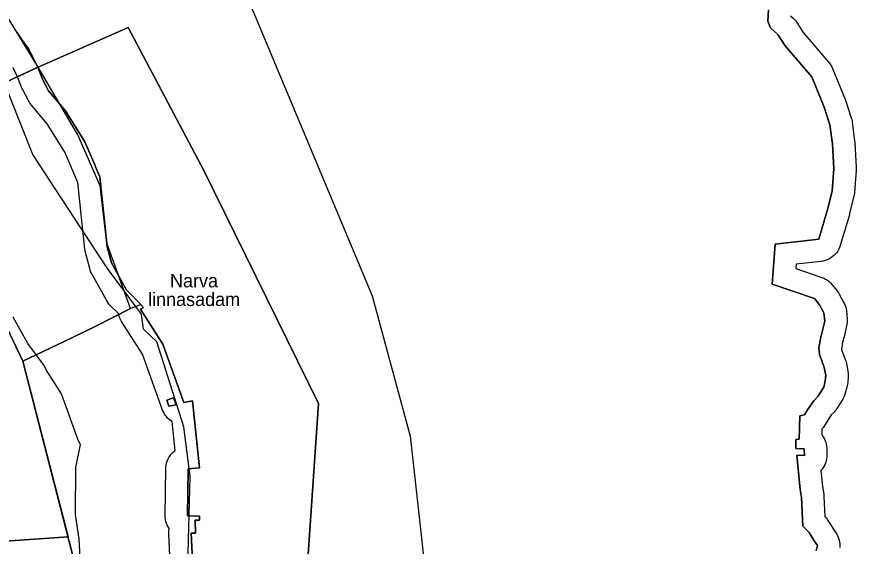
# Model space of a CAD drawing. Extents: x 728832 to 739469, y 6586263 to 6599699.
# Drawn here: x 738858.8 to 739233, y 6590183.4 to 6590419.5 of the extents above; entities that cross this region are included whole.
import ezdxf

# ---------------------------------------------------------------- set-up
doc = ezdxf.new("R2010")
doc.units = 0
for name, color, linetype in [('a_kalda_ekv', 7, 'Continuous'), ('a_kalda_veekaitsev', 7, 'Continuous'), ('a_piir', 7, 'Continuous'), ('a_veekogu_piir', 7, 'Continuous'), ('dp_hoonestus', 7, 'Continuous'), ('v_dp_kehtiv', 7, 'Continuous'), ('v_dp_situatsioon_tekst', 7, 'Continuous')]:
    doc.layers.add(name, color=color, linetype=linetype)

msp = doc.modelspace()

# ---------------------------------------------------------------- linework, layer by layer
at = {"layer": 'a_kalda_ekv'}
msp.add_lwpolyline([(738857.47, 6590092.24), (738873.8, 6590121.13), (738876.13, 6590124.85), (738880.71, 6590131.52), (738888.96, 6590141.03), (738886.6, 6590186.61), (738884.94, 6590197.52), (738885.19, 6590218.49), (738887.23, 6590228.8), (738886.16, 6590230.66), (738878.79, 6590251.31), (738871.89, 6590262.03), (738871.04, 6590263.97), (738863.76, 6590273.78), (738857.24, 6590285.58)], dxfattribs=at)
at = {"layer": 'a_kalda_veekaitsev'}
for points in [[(739215.15, 6590181.33), (739215.69, 6590183.77), (739214.32, 6590185.81), (739212, 6590189.49), (739209.18, 6590192.29), (739208.63, 6590205.04), (739208.06, 6590208.68), (739206.56, 6590223.97), (739209.92, 6590223.89), (739209.85, 6590226.8), (739206.08, 6590227.03), (739206.08, 6590231.03), (739207.6, 6590231.17), (739207.8, 6590241.54), (739209.98, 6590241.97), (739211.36, 6590244.21), (739214.05, 6590248.22), (739215.92, 6590250.16), (739218.5, 6590254.28), (739219.23, 6590256.93), (739219.41, 6590259.67), (739218.79, 6590263.16), (739217.75, 6590266.12), (739216.63, 6590268.9), (739216.35, 6590271.95), (739217.16, 6590276.61), (739218.02, 6590279.58), (739218.97, 6590283.82), (739218.64, 6590287.43), (739216.66, 6590291.04), (739214.4, 6590293.83), (739195.58, 6590300.23), (739196.84, 6590318.11), (739216.27, 6590320.35), (739220.36, 6590334.09), (739222.26, 6590341.97), (739223, 6590351.7), (739222.39, 6590362.84), (739221.31, 6590371.39), (739218.7, 6590379.22), (739213.16, 6590392.71), (739204.86, 6590402.37), (739201.27, 6590406.63), (739198.11, 6590411.58), (739194.86, 6590414.54), (739193.57, 6590417.54), (739193.83, 6590422.66)], [(739203.71, 6590420), (739204.85, 6590418.96), (739205.47, 6590418.35), (739206.03, 6590417.68), (739206.53, 6590416.97), (739209.32, 6590412.6), (739220.77, 6590399.21), (739221.26, 6590398.58), (739221.7, 6590397.93), (739222.08, 6590397.23), (739222.41, 6590396.51), (739227.95, 6590383.02), (739228.04, 6590382.81), (739228.12, 6590382.59), (739228.19, 6590382.38), (739230.8, 6590374.54), (739230.98, 6590373.92), (739231.13, 6590373.28), (739231.23, 6590372.64), (739232.31, 6590364.09), (739232.33, 6590363.86), (739232.36, 6590363.63), (739232.37, 6590363.39), (739232.99, 6590352.26), (739233, 6590351.82), (739233, 6590351.38), (739232.97, 6590350.94), (739232.24, 6590341.21), (739232.18, 6590340.68), (739232.1, 6590340.14), (739231.98, 6590339.62), (739230.08, 6590331.74), (739230.03, 6590331.57), (739229.99, 6590331.41), (739229.94, 6590331.24), (739225.85, 6590317.5), (739225.56, 6590316.65), (739225.19, 6590315.84), (739224.75, 6590315.05), (739224.24, 6590314.32), (739223.67, 6590313.63), (739223.03, 6590312.99), (739222.35, 6590312.41), (739221.61, 6590311.9), (739220.83, 6590311.45), (739220.02, 6590311.08), (739219.17, 6590310.78), (739218.3, 6590310.56), (739217.41, 6590310.42), (739206.23, 6590309.13), (739206.09, 6590307.22), (739217.62, 6590303.3), (739218.5, 6590302.95), (739219.34, 6590302.53), (739220.13, 6590302.03), (739220.88, 6590301.45), (739221.57, 6590300.81), (739222.19, 6590300.11), (739224.44, 6590297.31), (739224.79, 6590296.85), (739225.12, 6590296.36), (739225.42, 6590295.86), (739227.4, 6590292.25), (739227.77, 6590291.52), (739228.07, 6590290.76), (739228.31, 6590289.97), (739228.49, 6590289.17), (739228.6, 6590288.36), (739228.93, 6590284.74), (739228.97, 6590283.96), (739228.95, 6590283.18), (739228.87, 6590282.4), (739228.73, 6590281.63), (739227.78, 6590277.39), (739227.73, 6590277.19), (739227.68, 6590277), (739227.63, 6590276.8), (739226.92, 6590274.35), (739226.46, 6590271.16), (739228.15, 6590266.69), (739228.35, 6590266.1), (739228.51, 6590265.51), (739228.64, 6590264.9), (739229.26, 6590261.42), (739229.37, 6590260.62), (739229.41, 6590259.81), (739229.39, 6590259.01), (739229.2, 6590256.26), (739229.14, 6590255.6), (739229.03, 6590254.94), (739228.87, 6590254.29), (739228.14, 6590251.63), (739227.84, 6590250.71), (739227.45, 6590249.82), (739226.97, 6590248.97), (739224.39, 6590244.85), (739224, 6590244.27), (739223.58, 6590243.73), (739223.12, 6590243.21), (739221.91, 6590241.97), (739218.36, 6590236.51), (739218.15, 6590236.2), (739217.92, 6590235.89), (739217.68, 6590235.6), (739217.64, 6590233.08), (739218.19, 6590232.32), (739218.67, 6590231.52), (739219.07, 6590230.68), (739219.39, 6590229.8), (739219.63, 6590228.9), (739219.78, 6590227.98), (739219.85, 6590227.05), (739219.92, 6590224.13), (739219.9, 6590223.28), (739219.81, 6590222.43), (739219.65, 6590221.59), (739219.42, 6590220.77), (739219.12, 6590219.97), (739218.75, 6590219.2), (739218.32, 6590218.47), (739217.83, 6590217.77), (739217.28, 6590217.12), (739217.98, 6590209.95), (739218.51, 6590206.6), (739218.56, 6590206.22), (739218.6, 6590205.85), (739218.62, 6590205.48), (739219.05, 6590196.58), (739219.54, 6590196.05), (739220, 6590195.5), (739220.41, 6590194.91), (739224.09, 6590189.19), (739224.51, 6590188.47), (739224.87, 6590187.72), (739225.17, 6590186.94), (739225.4, 6590186.14), (739225.57, 6590185.32), (739225.66, 6590184.49), (739225.69, 6590183.66), (739225.64, 6590182.82)], [(738858.79, 6590412.67), (738861.49, 6590408.69), (738864.17, 6590405.06), (738866.18, 6590401.28), (738868.17, 6590397.05), (738870.25, 6590391.71), (738873.01, 6590386.56), (738880.54, 6590377.65), (738889.2, 6590363.72), (738893.69, 6590353.22), (738893.97, 6590352.57), (738895.85, 6590348.16), (738899.11, 6590316.91), (738901, 6590309.76), (738907.52, 6590297.96), (738914.55, 6590290.76), (738915.12, 6590289.76), (738913.93, 6590289.09), (738923.94, 6590273.54), (738933.25, 6590247.48), (738937.14, 6590248.24), (738940.19, 6590218.37), (738935.19, 6590217.89), (738934.94, 6590196.92), (738940.19, 6590196.8), (738940.26, 6590195.05), (738938.31, 6590195.07), (738938.5, 6590189.23), (738936.53, 6590189.2), (738938.37, 6590151.54)], [(738928.77, 6590140.91), (738926.54, 6590188.74), (738926.54, 6590189.56), (738926.6, 6590190.39), (738926.73, 6590191.21), (738926.26, 6590191.95), (738925.85, 6590192.74), (738925.52, 6590193.56), (738925.26, 6590194.41), (738925.08, 6590195.27), (738924.97, 6590196.15), (738924.94, 6590197.04), (738925.19, 6590218.01), (738925.24, 6590218.86), (738925.36, 6590219.7), (738925.54, 6590220.53), (738925.8, 6590221.34), (738926.13, 6590222.13), (738926.52, 6590222.88), (738926.98, 6590223.6), (738927.5, 6590224.28), (738928.07, 6590224.91), (738928.69, 6590225.49), (738929.36, 6590226.01), (738928.04, 6590238.95), (738927.33, 6590239.42), (738926.67, 6590239.95), (738926.05, 6590240.54), (738925.49, 6590241.17), (738924.98, 6590241.85), (738924.54, 6590242.57), (738924.15, 6590243.33), (738923.83, 6590244.12), (738914.91, 6590269.09), (738905.52, 6590283.68), (738905.05, 6590284.49), (738904.66, 6590285.33), (738904.35, 6590286.22), (738904.13, 6590287.12), (738900.36, 6590290.97), (738899.77, 6590291.64), (738899.23, 6590292.36), (738898.77, 6590293.12), (738892.25, 6590304.92), (738891.88, 6590305.66), (738891.57, 6590306.42), (738891.33, 6590307.2), (738889.44, 6590314.35), (738889.32, 6590314.86), (738889.23, 6590315.36), (738889.16, 6590315.87), (738886.06, 6590345.62), (738880.3, 6590359.09), (738872.43, 6590371.75), (738865.37, 6590380.11), (738864.94, 6590380.65), (738864.55, 6590381.23), (738864.2, 6590381.84), (738861.44, 6590386.99), (738861.25, 6590387.34), (738861.09, 6590387.71), (738860.93, 6590388.08), (738858.97, 6590393.1), (738857.23, 6590396.81)]]:
    msp.add_lwpolyline(points, dxfattribs=at)
at = {"layer": 'a_piir'}
for points in [[(738714.39, 6590648.68), (738701.09, 6590633.5), (738709.17, 6590600.23), (738724.9, 6590576.43), (738753.65, 6590521.22), (738764.74, 6590499.89), (738777.5, 6590495.02), (738782.96, 6590492.93), (738797.98, 6590465.61), (738833.44, 6590401.09), (738836.76, 6590395.87), (738843.38, 6590385.47), (738861.23, 6590393.76), (738868.42, 6590397.1), (738805.45, 6590500.11), (738796.89, 6590523.24), (738791.68, 6590528.96), (738769.71, 6590541.44), (738762.96, 6590546.51), (738751.84, 6590562.22), (738726.66, 6590613.29), (738725.19, 6590623.95)], [(738868.42, 6590397.1), (738861.23, 6590393.76), (738843.38, 6590385.47), (738811.42, 6590370.68), (738843.25, 6590304.19), (738861.55, 6590265.91), (738879.95, 6590274.65), (738893.72, 6590281.43), (738909.55, 6590289.44), (738899.03, 6590318.58), (738896.01, 6590344.11), (738886.01, 6590366.86)], [(738843.25, 6590304.19), (738738, 6590297.5), (738693.54, 6590289.26), (738721.83, 6590229.41), (738728.22, 6590217.92), (738736.09, 6590207.4), (738745.32, 6590197.99), (738755.65, 6590189.94), (738767, 6590183.31), (738779.12, 6590178.25), (738877.58, 6590144.8), (738893.32, 6590142.09), (738861.55, 6590265.91)], [(738925.72, 6590248.59), (738928.64, 6590249.6), (738929.79, 6590246.4), (738926.66, 6590245.79)], [(738926.66, 6590245.79), (738929.79, 6590246.4), (738928.64, 6590249.6), (738925.72, 6590248.59)]]:
    msp.add_lwpolyline(points, close=True, dxfattribs=at)
msp.add_lwpolyline([(738938.37, 6590151.54), (738936.53, 6590189.2), (738938.5, 6590189.23), (738938.31, 6590195.07), (738940.26, 6590195.05), (738940.19, 6590196.8), (738934.94, 6590196.92), (738935.19, 6590217.89), (738940.19, 6590218.37), (738937.14, 6590248.24), (738933.25, 6590247.48), (738923.94, 6590273.54), (738913.93, 6590289.09), (738915.12, 6590289.76), (738914.55, 6590290.76), (738914.2, 6590291.12), (738913.54, 6590290.88), (738909.55, 6590289.44), (738893.72, 6590281.43), (738879.95, 6590274.65), (738861.55, 6590265.91), (738893.32, 6590142.09)], dxfattribs=at)
at = {"layer": 'a_veekogu_piir'}
for points in [[(739193.83, 6590422.66), (739193.57, 6590417.54), (739194.86, 6590414.54), (739198.11, 6590411.58), (739201.27, 6590406.63), (739204.86, 6590402.37), (739213.16, 6590392.71), (739218.7, 6590379.22), (739221.31, 6590371.39), (739222.39, 6590362.84), (739223, 6590351.7), (739222.26, 6590341.97), (739220.36, 6590334.09), (739216.27, 6590320.35), (739196.84, 6590318.11), (739195.58, 6590300.23), (739214.4, 6590293.83), (739216.66, 6590291.04), (739218.64, 6590287.43), (739218.97, 6590283.82), (739218.02, 6590279.58), (739217.16, 6590276.61), (739216.35, 6590271.95), (739216.63, 6590268.9), (739217.75, 6590266.12), (739218.79, 6590263.16), (739219.41, 6590259.67), (739219.23, 6590256.93), (739218.5, 6590254.28), (739215.92, 6590250.16), (739214.05, 6590248.22), (739211.36, 6590244.21), (739209.98, 6590241.97), (739207.8, 6590241.54), (739207.6, 6590231.17), (739206.08, 6590231.03), (739206.08, 6590227.03), (739209.85, 6590226.8), (739209.92, 6590223.89), (739206.56, 6590223.97), (739208.06, 6590208.68), (739208.63, 6590205.04), (739209.18, 6590192.29), (739212, 6590189.49), (739214.32, 6590185.81), (739215.69, 6590183.77), (739215.15, 6590181.33)], [(738938.37, 6590151.54), (738936.53, 6590189.2), (738938.5, 6590189.23), (738938.31, 6590195.07), (738940.26, 6590195.05), (738940.19, 6590196.8), (738934.94, 6590196.92), (738935.19, 6590217.89), (738940.19, 6590218.37), (738937.14, 6590248.24), (738933.25, 6590247.48), (738923.94, 6590273.54), (738913.93, 6590289.09), (738915.12, 6590289.76), (738914.55, 6590290.76), (738907.52, 6590297.96), (738901, 6590309.76), (738899.11, 6590316.91), (738895.85, 6590348.16), (738893.97, 6590352.57), (738893.69, 6590353.22), (738889.2, 6590363.72), (738880.54, 6590377.65), (738873.01, 6590386.56), (738870.25, 6590391.71), (738868.17, 6590397.05), (738866.18, 6590401.28), (738864.17, 6590405.06), (738861.49, 6590408.69), (738858.79, 6590412.67)]]:
    msp.add_lwpolyline(points, dxfattribs=at)
at = {"layer": 'dp_hoonestus'}
for points in [[(738544.55, 6591130.54), (738777.58, 6590706.02), (738824.58, 6590644.12), (738867.62, 6590606.55), (738942.09, 6590474.98), (739017.23, 6590295.07), (739034.11, 6590232.51), (739063.74, 6589965.72), (739039.57, 6589879.66), (738995.22, 6589833.98), (738899.89, 6589713.66), (738848.75, 6589599.46), (738792.31, 6589420.72)], [(738544.55, 6591130.54), (738777.58, 6590706.02), (738824.58, 6590644.12), (738867.62, 6590606.55), (738942.09, 6590474.98), (739017.23, 6590295.07), (739034.11, 6590232.51), (739063.74, 6589965.72), (739039.57, 6589879.66), (738995.22, 6589833.98), (738899.89, 6589713.66), (738848.75, 6589599.46), (738792.31, 6589420.72)], [(738856.03, 6589934.94), (738859.34, 6589953.97), (738863.97, 6589973.5), (738870.93, 6589994.68), (738880.86, 6590018.35), (738893.43, 6590052.28), (738895.42, 6590066.02), (738900.39, 6590075.95), (738922.23, 6590113.02), (738932.66, 6590139.17), (738934.81, 6590161.02), (738935.31, 6590186.17), (738936.13, 6590214.47), (738933.32, 6590236.65), (738921.24, 6590274.55), (738915.28, 6590280.18), (738914.45, 6590286.96), (738899.23, 6590307.32), (738878.54, 6590338.77), (738865.96, 6590358.13), (738851.06, 6590395.2)], [(738856.03, 6589934.94), (738859.34, 6589953.97), (738863.97, 6589973.5), (738870.93, 6589994.68), (738880.86, 6590018.35), (738893.43, 6590052.28), (738895.42, 6590066.02), (738900.39, 6590075.95), (738922.23, 6590113.02), (738932.66, 6590139.17), (738934.81, 6590161.02), (738935.31, 6590186.17), (738936.13, 6590214.47), (738933.32, 6590236.65), (738921.24, 6590274.55), (738915.28, 6590280.18), (738914.45, 6590286.96), (738899.23, 6590307.32), (738878.54, 6590338.77), (738865.96, 6590358.13), (738851.06, 6590395.2)]]:
    msp.add_lwpolyline(points, dxfattribs=at)
at = {"layer": 'v_dp_kehtiv'}
for points in [[(738834.26, 6590139.1), (738901.84, 6590117.49), (738833.77, 6589993.69), (738849.37, 6589989.36), (738911.94, 6589971.59), (738937.72, 6590021.18), (738984.2, 6590114.69), (738993.34, 6590247.02), (738942.21, 6590350.94), (738908.53, 6590414.77), (738868.42, 6590397.1), (738843.38, 6590385.47), (738811.42, 6590370.68), (738843.25, 6590304.19), (738861.55, 6590265.91), (738881.66, 6590187.51), (738849.36, 6590185.31)], [(738833.77, 6589993.69), (738901.84, 6590117.49), (738834.26, 6590139.1), (738849.36, 6590185.31), (738881.66, 6590187.51), (738861.55, 6590265.91), (738843.25, 6590304.19), (738811.42, 6590370.68), (738868.42, 6590397.1), (738908.53, 6590414.77), (738942.21, 6590350.94), (738993.34, 6590247.02), (738984.2, 6590114.69), (738937.72, 6590021.18), (738911.94, 6589971.59), (738869.57, 6589983.62), (738849.37, 6589989.36)]]:
    msp.add_lwpolyline(points, close=True, dxfattribs=at)

# ---------------------------------------------------------------- texts
at = {"layer": 'v_dp_situatsioon_tekst'}
for s, p in [('Narva ', (738927.12, 6590298.84)), ('linnasadam', (738917.33, 6590290.52))]:
    msp.add_text(s, height=6, dxfattribs=at).set_placement(p)

doc.saveas('drawing.dxf')
